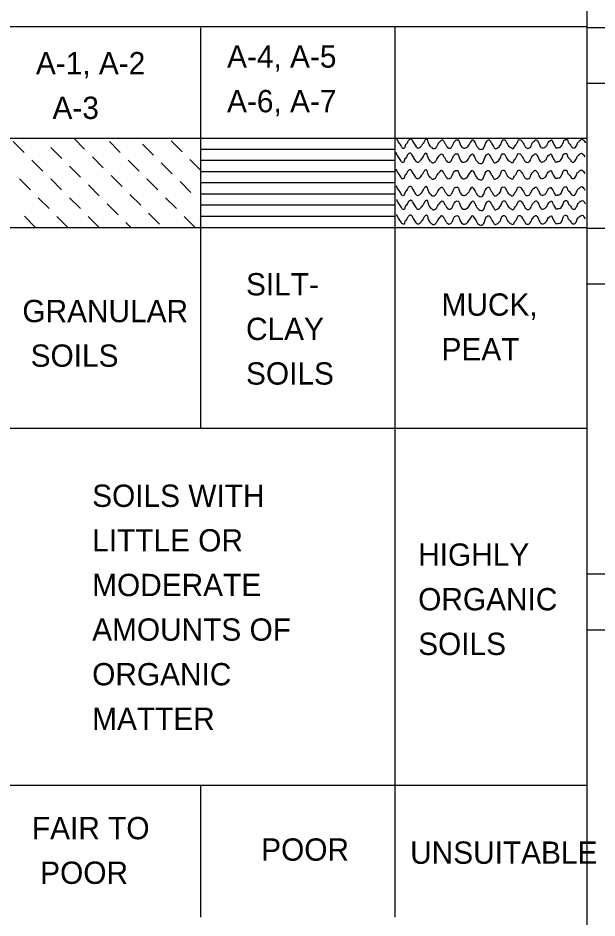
# Model space of a CAD drawing. Extents: x 278710 to 279187, y 171464 to 171625.
# Drawn here: x 279032.01 to 279043.27, y 171537.43 to 171554.93 of the extents above; entities that cross this region are included whole.
import ezdxf

# ---------------------------------------------------------------- set-up
doc = ezdxf.new("R2010")
doc.units = 0
doc.layers.add('Geotech Sheets and Borders Cell', color=7, linetype='Continuous')

msp = doc.modelspace()

# ---------------------------------------------------------------- linework, layer by layer
at = {"layer": 'Geotech Sheets and Borders Cell'}
for p, q in [((279043.07, 171566.02), (279043.07, 171485.806)), ((279005.33, 171554.763), (279043.07, 171554.763)), ((279035.566, 171546.942), (279035.566, 171554.737)), ((279039.34, 171537.446), (279039.34, 171554.763)), ((279081.678, 171554.741), (279043.07, 171554.741)), ((279081.678, 171553.657), (279043.07, 171553.657)), ((279005.33, 171552.594), (279043.07, 171552.594)), ((279032.125, 171552.316), (279031.913, 171552.529)), ((279033.089, 171552.594), (279033.301, 171552.382)), ((279033.995, 171552.316), (279033.783, 171552.529)), ((279034.429, 171552.477), (279034.642, 171552.264)), ((279035.197, 171552.329), (279034.984, 171552.542)), ((279032.859, 171552.199), (279032.646, 171552.412)), ((279035.566, 171552.382), (279039.34, 171552.382)), ((279039.366, 171552.312), (279039.361, 171552.308)), ((279032.49, 171551.952), (279032.277, 171552.165)), ((279033.453, 171552.23), (279033.665, 171552.017)), ((279034.36, 171551.952), (279034.147, 171552.165)), ((279034.793, 171552.113), (279035.006, 171551.9)), ((279035.561, 171551.965), (279035.349, 171552.178)), ((279035.566, 171552.165), (279039.34, 171552.165)), ((279033.223, 171551.835), (279033.01, 171552.048)), ((279035.566, 171551.948), (279039.34, 171551.948)), ((279039.366, 171551.991), (279039.361, 171551.987)), ((279032.247, 171551.588), (279032.034, 171551.8)), ((279032.854, 171551.588), (279032.642, 171551.8)), ((279033.817, 171551.865), (279034.03, 171551.653)), ((279034.724, 171551.588), (279034.511, 171551.8)), ((279035.158, 171551.748), (279035.37, 171551.536)), ((279033.375, 171551.683), (279033.587, 171551.471)), ((279035.566, 171551.731), (279039.34, 171551.731)), ((279039.37, 171551.666), (279039.366, 171551.661)), ((279032.611, 171551.223), (279032.399, 171551.436)), ((279033.219, 171551.223), (279033.006, 171551.436)), ((279034.182, 171551.501), (279034.394, 171551.288)), ((279035.088, 171551.223), (279034.876, 171551.436)), ((279035.566, 171551.514), (279039.34, 171551.514)), ((279039.379, 171551.397), (279039.374, 171551.392)), ((279033.739, 171551.319), (279033.952, 171551.106)), ((279035.566, 171551.297), (279039.34, 171551.297)), ((279032.342, 171550.863), (279032.13, 171551.076)), ((279032.976, 171550.859), (279032.763, 171551.071)), ((279033.583, 171550.859), (279033.37, 171551.071)), ((279034.546, 171551.137), (279034.759, 171550.924)), ((279035.453, 171550.859), (279035.24, 171551.071)), ((279035.566, 171551.08), (279039.34, 171551.08)), ((279039.348, 171551.08), (279039.344, 171551.076)), ((279039.374, 171551.111), (279039.37, 171551.106)), ((279034.104, 171550.954), (279034.203, 171550.859)), ((279039.344, 171551.037), (279039.34, 171551.041)), ((279005.33, 171550.859), (279043.07, 171550.859)), ((279081.678, 171550.837), (279043.07, 171550.837)), ((279081.678, 171549.753), (279043.07, 171549.753)), ((279005.33, 171546.955), (279043.07, 171546.955)), ((279081.678, 171544.113), (279043.07, 171544.113)), ((279079.076, 171544.113), (279043.07, 171544.113)), ((279081.678, 171543.029), (279043.07, 171543.029)), ((279005.33, 171540.014), (279043.07, 171540.014)), ((279035.566, 171537.446), (279035.566, 171540.001))]:
    msp.add_line(p, q, dxfattribs=at)
for points in [[(279040.042, 171552.416), (279040.016, 171552.451), (279039.986, 171552.525), (279039.969, 171552.568), (279039.951, 171552.572), (279039.93, 171552.559), (279039.899, 171552.512), (279039.838, 171552.425), (279039.817, 171552.403), (279039.791, 171552.395), (279039.773, 171552.403), (279039.756, 171552.425), (279039.682, 171552.546), (279039.665, 171552.568), (279039.656, 171552.572), (279039.635, 171552.572), (279039.609, 171552.555), (279039.574, 171552.499), (279039.53, 171552.425), (279039.526, 171552.403), (279039.5, 171552.395), (279039.478, 171552.408), (279039.465, 171552.434), (279039.413, 171552.512), (279039.374, 171552.581)], [(279040.047, 171552.416), (279040.077, 171552.39), (279040.138, 171552.412), (279040.168, 171552.46), (279040.229, 171552.542), (279040.255, 171552.564), (279040.29, 171552.529), (279040.32, 171552.477), (279040.355, 171552.425), (279040.389, 171552.399), (279040.433, 171552.412), (279040.467, 171552.464), (279040.533, 171552.559), (279040.567, 171552.559), (279040.593, 171552.516), (279040.663, 171552.403), (279040.697, 171552.399), (279040.732, 171552.412), (279040.832, 171552.542), (279040.858, 171552.564), (279040.871, 171552.542), (279040.897, 171552.503), (279040.949, 171552.412), (279041.036, 171552.377), (279041.066, 171552.403), (279041.127, 171552.538), (279041.175, 171552.559), (279041.192, 171552.538), (279041.253, 171552.434), (279041.287, 171552.39), (279041.344, 171552.412), (279041.404, 171552.486), (279041.439, 171552.559), (279041.47, 171552.564), (279041.504, 171552.525), (279041.556, 171552.434), (279041.604, 171552.403), (279041.634, 171552.39), (279041.678, 171552.447), (279041.717, 171552.503), (279041.743, 171552.559), (279041.782, 171552.564), (279041.804, 171552.542), (279041.86, 171552.451), (279041.895, 171552.403), (279041.955, 171552.403), (279042.007, 171552.49), (279042.06, 171552.551), (279042.077, 171552.564), (279042.12, 171552.529), (279042.151, 171552.464), (279042.203, 171552.403), (279042.246, 171552.412), (279042.298, 171552.46), (279042.35, 171552.542), (279042.372, 171552.551), (279042.385, 171552.559), (279042.402, 171552.529), (279042.424, 171552.49), (279042.493, 171552.403), (279042.511, 171552.412), (279042.541, 171552.412), (279042.615, 171552.525), (279042.641, 171552.564), (279042.693, 171552.559), (279042.706, 171552.516), (279042.754, 171552.46), (279042.801, 171552.403), (279042.832, 171552.403), (279042.866, 171552.438), (279042.897, 171552.512)], [(279042.897, 171552.512), (279042.944, 171552.551), (279042.984, 171552.572), (279043.018, 171552.542), (279043.044, 171552.503)], [(279040.029, 171552.143), (279040.003, 171552.178), (279039.973, 171552.251), (279039.956, 171552.295), (279039.938, 171552.299), (279039.917, 171552.286), (279039.886, 171552.238), (279039.825, 171552.152), (279039.804, 171552.13), (279039.778, 171552.121), (279039.76, 171552.13), (279039.743, 171552.152), (279039.669, 171552.273), (279039.652, 171552.295), (279039.643, 171552.299), (279039.622, 171552.299), (279039.596, 171552.282), (279039.561, 171552.225), (279039.517, 171552.152), (279039.513, 171552.13), (279039.487, 171552.121), (279039.465, 171552.134), (279039.452, 171552.16), (279039.4, 171552.238), (279039.361, 171552.308)], [(279040.034, 171552.143), (279040.064, 171552.117), (279040.125, 171552.139), (279040.155, 171552.186), (279040.216, 171552.269), (279040.242, 171552.29), (279040.277, 171552.256), (279040.307, 171552.204), (279040.342, 171552.152), (279040.376, 171552.126), (279040.42, 171552.139), (279040.454, 171552.191), (279040.52, 171552.286), (279040.554, 171552.286), (279040.58, 171552.243), (279040.65, 171552.13), (279040.684, 171552.126), (279040.719, 171552.139), (279040.819, 171552.269), (279040.845, 171552.29), (279040.858, 171552.269), (279040.884, 171552.23), (279040.936, 171552.139), (279041.023, 171552.104), (279041.053, 171552.13), (279041.114, 171552.264), (279041.162, 171552.286), (279041.179, 171552.264), (279041.24, 171552.16), (279041.274, 171552.117), (279041.331, 171552.139), (279041.391, 171552.212), (279041.426, 171552.286), (279041.457, 171552.29), (279041.491, 171552.251), (279041.543, 171552.16), (279041.591, 171552.13), (279041.621, 171552.117), (279041.665, 171552.173), (279041.704, 171552.23), (279041.73, 171552.286), (279041.769, 171552.29), (279041.791, 171552.269), (279041.847, 171552.178), (279041.882, 171552.13), (279041.942, 171552.13), (279041.994, 171552.217), (279042.046, 171552.277), (279042.064, 171552.29), (279042.107, 171552.256), (279042.138, 171552.191), (279042.19, 171552.13), (279042.233, 171552.139), (279042.285, 171552.186), (279042.337, 171552.269), (279042.359, 171552.277), (279042.372, 171552.286), (279042.389, 171552.256), (279042.411, 171552.217), (279042.48, 171552.13), (279042.498, 171552.139), (279042.528, 171552.139), (279042.602, 171552.251), (279042.628, 171552.29), (279042.68, 171552.286), (279042.693, 171552.243), (279042.741, 171552.186), (279042.788, 171552.13), (279042.819, 171552.13), (279042.853, 171552.165), (279042.884, 171552.238)], [(279042.884, 171552.238), (279042.931, 171552.277), (279042.97, 171552.299), (279043.005, 171552.269), (279043.031, 171552.23)], [(279040.029, 171551.822), (279040.003, 171551.857), (279039.973, 171551.93), (279039.956, 171551.974), (279039.938, 171551.978), (279039.917, 171551.965), (279039.886, 171551.917), (279039.825, 171551.831), (279039.804, 171551.809), (279039.778, 171551.8), (279039.76, 171551.809), (279039.743, 171551.831), (279039.669, 171551.952), (279039.652, 171551.974), (279039.643, 171551.978), (279039.622, 171551.978), (279039.596, 171551.961), (279039.561, 171551.904), (279039.517, 171551.831), (279039.513, 171551.809), (279039.487, 171551.8), (279039.465, 171551.813), (279039.452, 171551.839), (279039.4, 171551.917), (279039.361, 171551.987)], [(279040.034, 171551.822), (279040.064, 171551.796), (279040.125, 171551.818), (279040.155, 171551.865), (279040.216, 171551.948), (279040.242, 171551.969), (279040.277, 171551.935), (279040.307, 171551.883), (279040.342, 171551.831), (279040.376, 171551.805), (279040.42, 171551.818), (279040.454, 171551.87), (279040.52, 171551.965), (279040.554, 171551.965), (279040.58, 171551.922), (279040.65, 171551.809), (279040.684, 171551.805), (279040.719, 171551.818), (279040.819, 171551.948), (279040.845, 171551.969), (279040.858, 171551.948), (279040.884, 171551.909), (279040.936, 171551.818), (279041.023, 171551.783), (279041.053, 171551.809), (279041.114, 171551.943), (279041.162, 171551.965), (279041.179, 171551.943), (279041.24, 171551.839), (279041.274, 171551.796), (279041.331, 171551.818), (279041.391, 171551.891), (279041.426, 171551.965), (279041.457, 171551.969), (279041.491, 171551.93), (279041.543, 171551.839), (279041.591, 171551.809), (279041.621, 171551.796), (279041.665, 171551.852), (279041.704, 171551.909), (279041.73, 171551.965), (279041.769, 171551.969), (279041.791, 171551.948), (279041.847, 171551.857), (279041.882, 171551.809), (279041.942, 171551.809), (279041.994, 171551.896), (279042.046, 171551.956), (279042.064, 171551.969), (279042.107, 171551.935), (279042.138, 171551.87), (279042.19, 171551.809), (279042.233, 171551.818), (279042.285, 171551.865), (279042.337, 171551.948), (279042.359, 171551.956), (279042.372, 171551.965), (279042.389, 171551.935), (279042.411, 171551.896), (279042.48, 171551.809), (279042.498, 171551.818), (279042.528, 171551.818), (279042.602, 171551.93), (279042.628, 171551.969), (279042.68, 171551.965), (279042.693, 171551.922), (279042.741, 171551.865), (279042.788, 171551.809), (279042.819, 171551.809), (279042.853, 171551.844), (279042.884, 171551.917)], [(279042.884, 171551.917), (279042.931, 171551.956), (279042.97, 171551.978), (279043.005, 171551.948), (279043.031, 171551.909)], [(279040.034, 171551.497), (279040.008, 171551.531), (279039.977, 171551.605), (279039.96, 171551.648), (279039.943, 171551.653), (279039.921, 171551.64), (279039.891, 171551.592), (279039.83, 171551.505), (279039.808, 171551.484), (279039.782, 171551.475), (279039.765, 171551.484), (279039.747, 171551.505), (279039.674, 171551.627), (279039.656, 171551.648), (279039.648, 171551.653), (279039.626, 171551.653), (279039.6, 171551.635), (279039.565, 171551.579), (279039.522, 171551.505), (279039.517, 171551.484), (279039.491, 171551.475), (279039.47, 171551.488), (279039.457, 171551.514), (279039.405, 171551.592), (279039.366, 171551.661)], [(279040.038, 171551.497), (279040.068, 171551.471), (279040.129, 171551.492), (279040.159, 171551.54), (279040.22, 171551.622), (279040.246, 171551.644), (279040.281, 171551.609), (279040.311, 171551.557), (279040.346, 171551.505), (279040.381, 171551.479), (279040.424, 171551.492), (279040.459, 171551.544), (279040.524, 171551.64), (279040.559, 171551.64), (279040.585, 171551.596), (279040.654, 171551.484), (279040.689, 171551.479), (279040.723, 171551.492), (279040.823, 171551.622), (279040.849, 171551.644), (279040.862, 171551.622), (279040.888, 171551.583), (279040.94, 171551.492), (279041.027, 171551.458), (279041.057, 171551.484), (279041.118, 171551.618), (279041.166, 171551.64), (279041.183, 171551.618), (279041.244, 171551.514), (279041.279, 171551.471), (279041.335, 171551.492), (279041.396, 171551.566), (279041.431, 171551.64), (279041.461, 171551.644), (279041.496, 171551.605), (279041.548, 171551.514), (279041.595, 171551.484), (279041.626, 171551.471), (279041.669, 171551.527), (279041.708, 171551.583), (279041.734, 171551.64), (279041.773, 171551.644), (279041.795, 171551.622), (279041.851, 171551.531), (279041.886, 171551.484), (279041.947, 171551.484), (279041.999, 171551.57), (279042.051, 171551.631), (279042.068, 171551.644), (279042.112, 171551.609), (279042.142, 171551.544), (279042.194, 171551.484), (279042.237, 171551.492), (279042.289, 171551.54), (279042.341, 171551.622), (279042.363, 171551.631), (279042.376, 171551.64), (279042.394, 171551.609), (279042.415, 171551.57), (279042.485, 171551.484), (279042.502, 171551.492), (279042.532, 171551.492), (279042.606, 171551.605), (279042.632, 171551.644), (279042.684, 171551.64), (279042.697, 171551.596), (279042.745, 171551.54), (279042.793, 171551.484), (279042.823, 171551.484), (279042.858, 171551.518), (279042.888, 171551.592)], [(279042.888, 171551.592), (279042.936, 171551.631), (279042.975, 171551.653), (279043.01, 171551.622), (279043.036, 171551.583)], [(279040.042, 171551.228), (279040.016, 171551.262), (279039.986, 171551.336), (279039.969, 171551.379), (279039.951, 171551.384), (279039.93, 171551.371), (279039.899, 171551.323), (279039.838, 171551.236), (279039.817, 171551.215), (279039.791, 171551.206), (279039.773, 171551.215), (279039.756, 171551.236), (279039.682, 171551.358), (279039.665, 171551.379), (279039.656, 171551.384), (279039.635, 171551.384), (279039.609, 171551.366), (279039.574, 171551.31), (279039.53, 171551.236), (279039.526, 171551.215), (279039.5, 171551.206), (279039.478, 171551.219), (279039.465, 171551.245), (279039.413, 171551.323), (279039.374, 171551.392)], [(279040.047, 171551.228), (279040.077, 171551.202), (279040.138, 171551.223), (279040.168, 171551.271), (279040.229, 171551.353), (279040.255, 171551.375), (279040.29, 171551.34), (279040.32, 171551.288), (279040.355, 171551.236), (279040.389, 171551.21), (279040.433, 171551.223), (279040.467, 171551.275), (279040.533, 171551.371), (279040.567, 171551.371), (279040.593, 171551.327), (279040.663, 171551.215), (279040.697, 171551.21), (279040.732, 171551.223), (279040.832, 171551.353), (279040.858, 171551.375), (279040.871, 171551.353), (279040.897, 171551.314), (279040.949, 171551.223), (279041.036, 171551.189), (279041.066, 171551.215), (279041.127, 171551.349), (279041.175, 171551.371), (279041.192, 171551.349), (279041.253, 171551.245), (279041.287, 171551.202), (279041.344, 171551.223), (279041.404, 171551.297), (279041.439, 171551.371), (279041.47, 171551.375), (279041.504, 171551.336), (279041.556, 171551.245), (279041.604, 171551.215), (279041.634, 171551.202), (279041.678, 171551.258), (279041.717, 171551.314), (279041.743, 171551.371), (279041.782, 171551.375), (279041.804, 171551.353), (279041.86, 171551.262), (279041.895, 171551.215), (279041.955, 171551.215), (279042.007, 171551.301), (279042.06, 171551.362), (279042.077, 171551.375), (279042.12, 171551.34), (279042.151, 171551.275), (279042.203, 171551.215), (279042.246, 171551.223), (279042.298, 171551.271), (279042.35, 171551.353), (279042.372, 171551.362), (279042.385, 171551.371), (279042.402, 171551.34), (279042.424, 171551.301), (279042.493, 171551.215), (279042.511, 171551.223), (279042.541, 171551.223), (279042.615, 171551.336), (279042.641, 171551.375), (279042.693, 171551.371), (279042.706, 171551.327), (279042.754, 171551.271), (279042.801, 171551.215), (279042.832, 171551.215), (279042.866, 171551.249), (279042.897, 171551.323)], [(279042.897, 171551.323), (279042.944, 171551.362), (279042.984, 171551.384), (279043.018, 171551.353), (279043.044, 171551.314)], [(279040.038, 171550.941), (279040.012, 171550.976), (279039.982, 171551.05), (279039.964, 171551.093), (279039.947, 171551.097), (279039.925, 171551.084), (279039.895, 171551.037), (279039.834, 171550.95), (279039.812, 171550.928), (279039.786, 171550.92), (279039.769, 171550.928), (279039.752, 171550.95), (279039.678, 171551.071), (279039.661, 171551.093), (279039.652, 171551.097), (279039.63, 171551.097), (279039.604, 171551.08), (279039.57, 171551.024), (279039.526, 171550.95), (279039.522, 171550.928), (279039.496, 171550.92), (279039.474, 171550.933), (279039.461, 171550.959), (279039.409, 171551.037), (279039.37, 171551.106)], [(279040.042, 171550.941), (279040.073, 171550.915), (279040.133, 171550.937), (279040.164, 171550.985), (279040.225, 171551.067), (279040.251, 171551.089), (279040.285, 171551.054), (279040.316, 171551.002), (279040.35, 171550.95), (279040.385, 171550.924), (279040.428, 171550.937), (279040.463, 171550.989), (279040.528, 171551.084), (279040.563, 171551.084), (279040.589, 171551.041), (279040.658, 171550.928), (279040.693, 171550.924), (279040.728, 171550.937), (279040.828, 171551.067), (279040.854, 171551.089), (279040.867, 171551.067), (279040.893, 171551.028), (279040.945, 171550.937), (279041.031, 171550.902), (279041.062, 171550.928), (279041.123, 171551.063), (279041.17, 171551.084), (279041.188, 171551.063), (279041.248, 171550.959), (279041.283, 171550.915), (279041.339, 171550.937), (279041.4, 171551.011), (279041.435, 171551.084), (279041.465, 171551.089), (279041.5, 171551.05), (279041.552, 171550.959), (279041.6, 171550.928), (279041.63, 171550.915), (279041.673, 171550.972), (279041.712, 171551.028), (279041.739, 171551.084), (279041.778, 171551.089), (279041.799, 171551.067), (279041.856, 171550.976), (279041.89, 171550.928), (279041.951, 171550.928), (279042.003, 171551.015), (279042.055, 171551.076), (279042.073, 171551.089), (279042.116, 171551.054), (279042.146, 171550.989), (279042.198, 171550.928), (279042.242, 171550.937), (279042.294, 171550.985), (279042.346, 171551.067), (279042.368, 171551.076), (279042.381, 171551.084), (279042.398, 171551.054), (279042.42, 171551.015), (279042.489, 171550.928), (279042.506, 171550.937), (279042.537, 171550.937), (279042.61, 171551.05), (279042.636, 171551.089), (279042.689, 171551.084), (279042.702, 171551.041), (279042.749, 171550.985), (279042.797, 171550.928), (279042.827, 171550.928), (279042.862, 171550.963), (279042.892, 171551.037)], [(279042.892, 171551.037), (279042.94, 171551.076), (279042.979, 171551.097), (279043.014, 171551.067), (279043.04, 171551.028)]]:
    msp.add_spline(points, degree=3, dxfattribs=at)

# ---------------------------------------------------------------- texts
for s, p in [('A-4, A-5', (279036.073, 171553.965)), ('A-1, A-2', (279032.355, 171553.835)), ('A-6, A-7', (279036.073, 171553.097)), ('  A-3', (279032.355, 171552.967)), ('SILT-', (279036.442, 171549.536)), ('MUCK,', (279040.246, 171549.141)), ('GRANULAR', (279032.091, 171549.015)), ('CLAY', (279036.442, 171548.668)), ('PEAT', (279040.246, 171548.273)), (' SOILS', (279032.091, 171548.148)), ('SOILS', (279036.442, 171547.801)), ('SOILS WITH', (279033.449, 171545.423)), ('LITTLE OR', (279033.449, 171544.556)), ('HIGHLY', (279039.791, 171544.278)), ('MODERATE', (279033.449, 171543.688)), ('ORGANIC', (279039.791, 171543.411)), ('AMOUNTS OF', (279033.449, 171542.821)), ('SOILS', (279039.791, 171542.543)), ('ORGANIC', (279033.449, 171541.953)), ('MATTER', (279033.449, 171541.085)), ('FAIR TO', (279032.277, 171538.96)), ('POOR', (279036.737, 171538.543)), ('UNSUITABLE', (279039.635, 171538.483)), (' POOR', (279032.277, 171538.092))]:
    msp.add_text(s, height=0.4338, dxfattribs=at).set_placement(p)

doc.saveas('drawing.dxf')
